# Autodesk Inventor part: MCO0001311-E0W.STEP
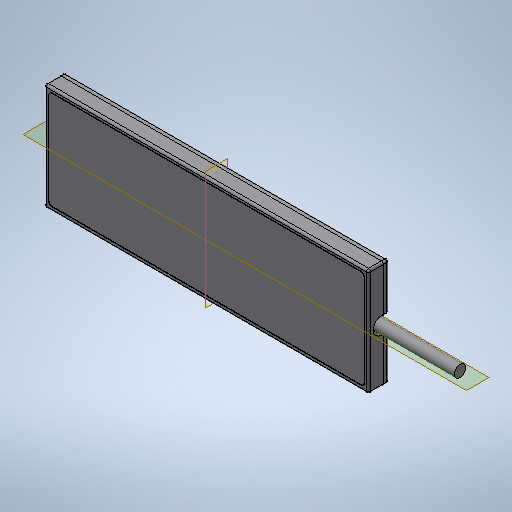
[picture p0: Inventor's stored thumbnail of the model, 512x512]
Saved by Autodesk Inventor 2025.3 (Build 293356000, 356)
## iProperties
RuleStatus: InUse
Created: 2015-07
Material: Generic
Vendor: THORLABS
Document SubType Name: Modeling
Designer: ARNOLDJ
Density: 1 g/cm^3
Appearance: Default
Description: MICRSCOPE SLIDE POWER SENSOR
AfterDocSave0: file://Part Number Cleaner
DESIGN DEPARTMENT: HHMI: JRC - ID&F
ALTERED ITEM PART NUMBER: N/A
ALTERED ITEM VENDOR: N/A
ALTERED ITEM DESCRIPTION: N/A
Title: MCO0001311-E0W.STEP
Description: STEP AP203
Creation Date: 2015-03-24
Sending System: SolidWorks 2014
Preprocessor: SwSTEP 2.0
Author: ARNOLDJ
Revision Number: 0
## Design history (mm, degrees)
feature "Base1"
feature "Base2"
feature "Base3"
feature "Base4"
feature "Base5"
feature "Base6"
feature "Base7"
feature "Base8"
feature "Base9"
feature "Base10"
feature "Base11"
feature "Base12"
feature "Base13"
feature "Base14"
feature "Base15"
feature "Base16"
workplane "Work Plane1"
workplane "Work Plane2"
node "Extrude19"
node "Extrude1"
node "Extrude3"
node "Extrude4"
node "Extrude5"
node "Thread-Simple"
node "Thread-Simple_1"
node "Thread-Simple_2"
node "Thread-Simple_3"
node "Thread-Simple_4"
node "Thread-Simple_5"
node "Thread-Simple_6"
node "Thread-Simple_7"
node "Schnitt-Linear austragen3"
node "Fillet1"
node "Extrude1_1"
